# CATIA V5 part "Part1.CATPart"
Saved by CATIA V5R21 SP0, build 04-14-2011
Part number: Part1
Material "Steel": density 7860 kg/m3, Young's modulus 2e+11 Pa, Poisson ratio 0.266, thermal expansion 1.17e-05 1/K
Bounding box of the stored display mesh (mm): x 0 to 500, y -25 to 225, z -4 to 54
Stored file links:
  G:\CATIA\Analysis\Part1.CATPart
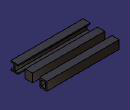
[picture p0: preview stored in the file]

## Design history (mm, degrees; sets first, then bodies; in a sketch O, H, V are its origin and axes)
AxisSystem1: origin (0, 0, 0), X (1, 0, 0), Y (0, 1, 0), Z (0, 0, 1)
Body1 (main body), material "Steel"
  Sketch1 on YZ plane of AxisSystem1, origin (0, 0, 0), H (0, 1, 0), V (0, 0, 1)
    line L1 (0, 0) -> (0, 50)
    line L2 (-25, 50) -> (25, 50)
    point P2 (-25, 50)
    point P3 (25, 50)
    line L3 (-25, 0) -> (25, 0)
    length L1 = 50
    length L2 = 50
    distance L2 H = 50
    length L3 = 50
    vertical: L1 V
    horizontal: L2 H, L3 H
    symmetry: P2 P3 L1
    midpoint: L3 O
  Pad1: profile Sketch1, direction (1, 0, 0), length 500, thin wall 8
  Sketch2 on YZ plane of AxisSystem1, origin (0, 0, 0), H (0, 1, 0), V (0, 0, 1)
    point P1 (100, 25)
    line L1 (125, 54) -> (125, -4)
    line L2 (125, -4) -> (75, -4)
    line L3 (75, -4) -> (75, 54)
    line L4 (75, 54) -> (125, 54)
    reference projected line E1 (-25, -4) -> (25, -4) from edge [face of Pad1 | end face of Pad1]
    reference projected line E2 through (0, 0) direction (0, 1) from edge [ZX plane of AxisSystem1 | YZ plane of AxisSystem1]
    length L1 = 58
    length L4 = 50
    distance E2 L3 = 75
    vertical: L1 V, L3 V
    horizontal: L2 H, L4 H
    equidistance: L1 L3 P1, L2 L4 P1
    coincidence: L2 E1
  Pad2: profile Sketch2, direction (1, 0, 0), length 500
  Sketch3 on YZ plane of AxisSystem1, origin (0, 0, 0), H (0, 1, 0), V (0, 0, 1)
    line L1 (185, 44) -> (185, 6)
    line L2 (185, 6) -> (215, 6)
    line L3 (215, 6) -> (215, 44)
    line L4 (215, 44) -> (185, 44)
    line L5 (175, 54) -> (225, 54)
    line L6 (225, 54) -> (225, -4)
    line L7 (225, -4) -> (175, -4)
    line L8 (175, -4) -> (175, 54)
    point P8 (175, -4)
    reference projected line E1 (-25, -4) -> (25, -4) from edge [face of Pad1 | end face of Pad1]
    reference projected line E2 (-25, 54) -> (25, 54) from edge [end face of Pad1 | face of Pad1]
    reference projected point E3 (125, -4) from vertex [face of Pad2 from Sketch2.L1 | face of Pad2 from Sketch2.L2 | end face of Pad2]
    length L3 = 38
    length L4 = 30
    distance E3 P8 = 50
    length L7 = 50
    distance L1 L8 = 10
    distance L4 L5 = 10
    vertical: L1 V, L3 V, L6 V, L8 V
    horizontal: L2 H, L4 H, L5 H, L7 H
    coincidence: L7 E1, L5 E2
  Pad3: profile Sketch3, direction (1, 0, 0), length 500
